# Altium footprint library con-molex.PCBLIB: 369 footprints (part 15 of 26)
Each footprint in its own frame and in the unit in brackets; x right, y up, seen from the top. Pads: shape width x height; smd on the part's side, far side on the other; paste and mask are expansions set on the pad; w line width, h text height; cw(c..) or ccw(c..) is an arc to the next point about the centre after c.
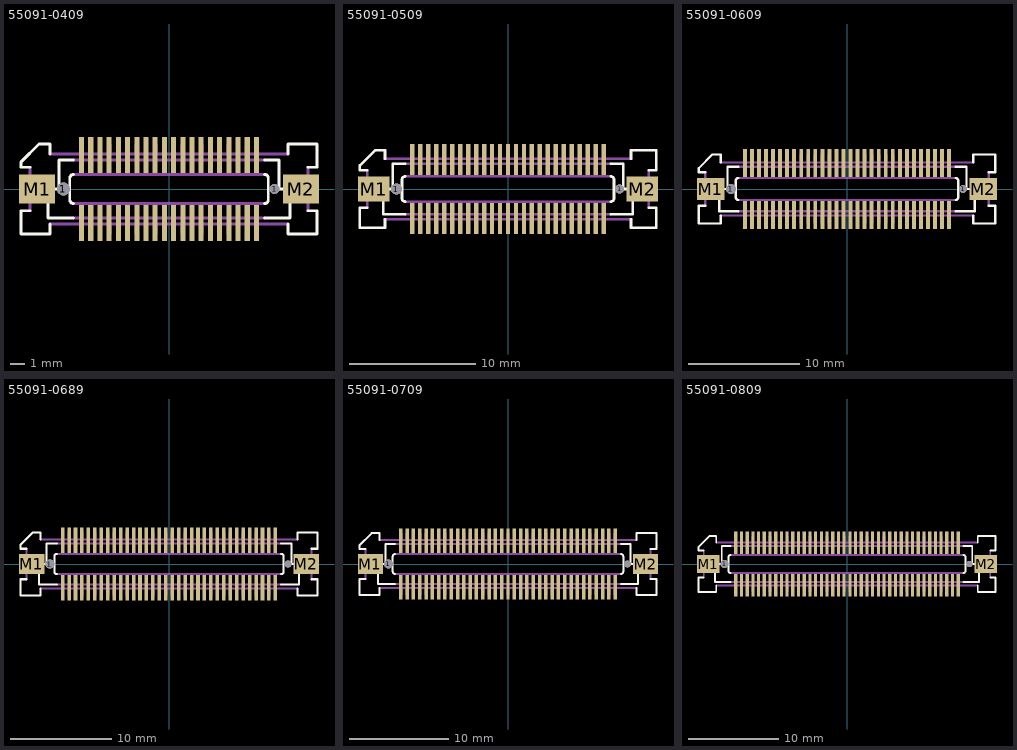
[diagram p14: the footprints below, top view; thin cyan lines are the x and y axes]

## 55091-0409 [mm]
pads (44):
  round 0.9 hole 0.9: 1(-7.285,0)
  rect 0.35x2.5 smd: 1(-6.032,2.35) 2(-6.032,-2.35) 3(-5.397,2.35) 4(-5.397,-2.35) 5(-4.763,2.35) 6(-4.763,-2.35) 7(-4.127,2.35) 8(-4.127,-2.35) 9(-3.492,2.35) 10(-3.492,-2.35) 11(-2.857,2.35) 12(-2.857,-2.35) 13(-2.222,2.35) 14(-2.222,-2.35) 15(-1.587,2.35) 16(-1.587,-2.35) 17(-0.953,2.35) 18(-0.953,-2.35) 19(-0.318,2.35) 20(-0.318,-2.35) 21(0.318,2.35) 22(0.318,-2.35) 23(0.953,2.35) 24(0.953,-2.35) 25(1.587,2.35) 26(1.587,-2.35) 27(2.222,2.35) 28(2.222,-2.35) 29(2.857,2.35) 30(2.857,-2.35) 31(3.492,2.35) 32(3.492,-2.35) 33(4.127,2.35) 34(4.127,-2.35) 35(4.763,2.35) 36(4.763,-2.35) 37(5.397,2.35) 38(5.397,-2.35) 39(6.032,2.35) 40(6.032,-2.35)
  round 0.7 hole 0.7: 1(7.285,0)
  rect 2.5x2 smd: M1(-9.1,0) M2(9.1,0)
Top Overlay:
  lines w0.203: -9.6,-1.5 -10.2,-1.5 -10.2,-3.1 -8.2,-3.1 -8.2,-2.4 ; -9.6,1.5 -10.2,1.5 -10.2,1.875 -8.975,3.1 -8.2,3.1 -8.2,2.4 ; -6.6,-2 -8.35,-2 -8.35,0 -7.6,0 -7.6,2 -6.6,2 ; -6.6,-1 cw(c-6.6,-0.75) -6.85,-0.75 -6.85,0.75 cw(c-6.6,0.75) -6.6,1 ; 6.6,-2 8.35,-2 8.35,0 7.6,0 7.6,2 6.6,2 ; 6.6,-1 ccw(c6.6,-0.75) 6.85,-0.75 6.85,0.75 ccw(c6.6,0.75) 6.6,1 ; 8.2,-2.4 8.2,-3.1 10.2,-3.1 10.2,-1.5 9.6,-1.5 ; 8.2,2.4 8.2,3.1 10.2,3.1 10.2,1.5 9.6,1.5
Top Solder:
  rectangle: -6.232,1.075 -5.833,3.625
  region: -5.833,-1.075 -6.232,-1.075 -6.232,-3.625 -5.833,-3.625
  rectangle: -5.597,1.075 -5.198,3.625
  region: -5.198,-1.075 -5.597,-1.075 -5.597,-3.625 -5.198,-3.625
  rectangle: -4.962,1.075 -4.563,3.625
  region: -4.563,-1.075 -4.962,-1.075 -4.962,-3.625 -4.563,-3.625
  rectangle: -4.327,1.075 -3.928,3.625
  region: -3.928,-1.075 -4.327,-1.075 -4.327,-3.625 -3.928,-3.625
  rectangle: -3.692,1.075 -3.293,3.625
  region: -3.293,-1.075 -3.692,-1.075 -3.692,-3.625 -3.293,-3.625
  rectangle: -3.057,1.075 -2.658,3.625
  region: -2.658,-1.075 -3.057,-1.075 -3.057,-3.625 -2.658,-3.625
  rectangle: -2.422,1.075 -2.023,3.625
  region: -2.023,-1.075 -2.422,-1.075 -2.422,-3.625 -2.023,-3.625
  rectangle: -1.787,1.075 -1.388,3.625
  region: -1.388,-1.075 -1.787,-1.075 -1.787,-3.625 -1.388,-3.625
  rectangle: -1.152,1.075 -0.753,3.625
  region: -0.753,-1.075 -1.152,-1.075 -1.152,-3.625 -0.753,-3.625
  rectangle: -0.517,1.075 -0.118,3.625
  region: -0.118,-1.075 -0.517,-1.075 -0.517,-3.625 -0.118,-3.625
  rectangle: 0.118,1.075 0.517,3.625
  region: 0.517,-1.075 0.118,-1.075 0.118,-3.625 0.517,-3.625
  rectangle: 0.753,1.075 1.152,3.625
  region: 1.152,-1.075 0.753,-1.075 0.753,-3.625 1.152,-3.625
  rectangle: 1.388,1.075 1.787,3.625
  region: 1.787,-1.075 1.388,-1.075 1.388,-3.625 1.787,-3.625
  rectangle: 2.023,1.075 2.422,3.625
  region: 2.422,-1.075 2.023,-1.075 2.023,-3.625 2.422,-3.625
  rectangle: 2.658,1.075 3.057,3.625
  region: 3.057,-1.075 2.658,-1.075 2.658,-3.625 3.057,-3.625
  rectangle: 3.293,1.075 3.692,3.625
  region: 3.692,-1.075 3.293,-1.075 3.293,-3.625 3.692,-3.625
  rectangle: 3.928,1.075 4.327,3.625
  region: 4.327,-1.075 3.928,-1.075 3.928,-3.625 4.327,-3.625
  rectangle: 4.563,1.075 4.962,3.625
  region: 4.962,-1.075 4.563,-1.075 4.563,-3.625 4.962,-3.625
  rectangle: 5.198,1.075 5.597,3.625
  region: 5.597,-1.075 5.198,-1.075 5.198,-3.625 5.597,-3.625
  rectangle: 5.833,1.075 6.232,3.625
  region: 6.232,-1.075 5.833,-1.075 5.833,-3.625 6.232,-3.625
Mechanical 16:
  rectangle: -6.183,-3.1 -5.882,-2.375
  region: -5.882,3.1 -6.183,3.1 -6.183,2.375 -5.882,2.375
  rectangle: -5.548,-3.1 -5.247,-2.375
  region: -5.247,3.1 -5.548,3.1 -5.548,2.375 -5.247,2.375
  rectangle: -4.913,-3.1 -4.612,-2.375
  region: -4.612,3.1 -4.913,3.1 -4.913,2.375 -4.612,2.375
  rectangle: -4.278,-3.1 -3.977,-2.375
  region: -3.977,3.1 -4.278,3.1 -4.278,2.375 -3.977,2.375
  rectangle: -3.643,-3.1 -3.342,-2.375
  region: -3.342,3.1 -3.643,3.1 -3.643,2.375 -3.342,2.375
  rectangle: -3.008,-3.1 -2.707,-2.375
  region: -2.707,3.1 -3.008,3.1 -3.008,2.375 -2.707,2.375
  rectangle: -2.373,-3.1 -2.072,-2.375
  region: -2.072,3.1 -2.373,3.1 -2.373,2.375 -2.072,2.375
  rectangle: -1.738,-3.1 -1.437,-2.375
  region: -1.437,3.1 -1.738,3.1 -1.738,2.375 -1.437,2.375
  rectangle: -1.103,-3.1 -0.802,-2.375
  region: -0.802,3.1 -1.103,3.1 -1.103,2.375 -0.802,2.375
  rectangle: -0.468,-3.1 -0.167,-2.375
  region: -0.167,3.1 -0.468,3.1 -0.468,2.375 -0.167,2.375
  rectangle: 0.167,-3.1 0.468,-2.375
  region: 0.468,3.1 0.167,3.1 0.167,2.375 0.468,2.375
  rectangle: 0.802,-3.1 1.103,-2.375
  region: 1.103,3.1 0.802,3.1 0.802,2.375 1.103,2.375
  rectangle: 1.437,-3.1 1.738,-2.375
  region: 1.738,3.1 1.437,3.1 1.437,2.375 1.738,2.375
  rectangle: 2.072,-3.1 2.373,-2.375
  region: 2.373,3.1 2.072,3.1 2.072,2.375 2.373,2.375
  rectangle: 2.707,-3.1 3.008,-2.375
  region: 3.008,3.1 2.707,3.1 2.707,2.375 3.008,2.375
  rectangle: 3.342,-3.1 3.643,-2.375
  region: 3.643,3.1 3.342,3.1 3.342,2.375 3.643,2.375
  rectangle: 3.977,-3.1 4.278,-2.375
  region: 4.278,3.1 3.977,3.1 3.977,2.375 4.278,2.375
  rectangle: 4.612,-3.1 4.913,-2.375
  region: 4.913,3.1 4.612,3.1 4.612,2.375 4.913,2.375
  rectangle: 5.247,-3.1 5.548,-2.375
  region: 5.548,3.1 5.247,3.1 5.247,2.375 5.548,2.375
  rectangle: 5.882,-3.1 6.183,-2.375
  region: 6.183,3.1 5.882,3.1 5.882,2.375 6.183,2.375
  lines w0.203: -9.6,-1.5 -9.6,1.5 ; -8.2,-2.4 8.2,-2.4 ; -8.2,2.4 8.2,2.4 ; -6.6,-2 6.6,-2 ; -6.6,-1 6.6,-1 ; -6.6,1 6.6,1 ; -6.6,2 6.6,2 ; 9.6,-1.5 9.6,1.5

## 55091-0509 [mm]
pads (54):
  round 0.9 hole 0.9: 1(-8.875,0)
  rect 0.35x2.5 smd: 1(-7.62,2.35) 2(-7.62,-2.35) 3(-6.985,2.35) 4(-6.985,-2.35) 5(-6.35,2.35) 6(-6.35,-2.35) 7(-5.715,2.35) 8(-5.715,-2.35) 9(-5.08,2.35) 10(-5.08,-2.35) 11(-4.445,2.35) 12(-4.445,-2.35) 13(-3.81,2.35) 14(-3.81,-2.35) 15(-3.175,2.35) 16(-3.175,-2.35) 17(-2.54,2.35) 18(-2.54,-2.35) 19(-1.905,2.35) 20(-1.905,-2.35) 21(-1.27,2.35) 22(-1.27,-2.35) 23(-0.635,2.35) 24(-0.635,-2.35) 25(0,2.35) 26(0,-2.35) 27(0.635,2.35) 28(0.635,-2.35) 29(1.27,2.35) 30(1.27,-2.35) 31(1.905,2.35) 32(1.905,-2.35) 33(2.54,2.35) 34(2.54,-2.35) 35(3.175,2.35) 36(3.175,-2.35) 37(3.81,2.35) 38(3.81,-2.35) 39(4.445,2.35) 40(4.445,-2.35) 41(5.08,2.35) 42(5.08,-2.35) 43(5.715,2.35) 44(5.715,-2.35) 45(6.35,2.35) 46(6.35,-2.35) 47(6.985,2.35) 48(6.985,-2.35) 49(7.62,2.35) 50(7.62,-2.35)
  round 0.7 hole 0.7: 1(8.875,0)
  rect 2.5x2 smd: M1(-10.688,0) M2(10.688,0)
Top Overlay:
  lines w0.203: -11.187,-1.5 -11.787,-1.5 -11.787,-3.1 -9.787,-3.1 -9.787,-2.4 ; -11.187,1.5 -11.787,1.5 -11.787,1.875 -10.563,3.1 -9.787,3.1 -9.787,2.4 ; -8.187,-2 -9.937,-2 -9.937,0 -9.187,0 -9.187,2 -8.187,2 ; -8.187,-1 cw(c-8.188,-0.75) -8.438,-0.75 -8.438,0.75 cw(c-8.188,0.75) -8.187,1 ; 8.187,-2 9.937,-2 9.937,0 9.187,0 9.187,2 8.187,2 ; 8.187,-1 ccw(c8.188,-0.75) 8.438,-0.75 8.438,0.75 ccw(c8.188,0.75) 8.187,1 ; 9.787,-2.4 9.787,-3.1 11.787,-3.1 11.787,-1.5 11.187,-1.5 ; 9.787,2.4 9.787,3.1 11.787,3.1 11.787,1.5 11.187,1.5
Top Solder:
  rectangle: -7.82,1.075 -7.42,3.625
  region: -7.42,-1.075 -7.82,-1.075 -7.82,-3.625 -7.42,-3.625
  rectangle: -7.185,1.075 -6.785,3.625
  region: -6.785,-1.075 -7.185,-1.075 -7.185,-3.625 -6.785,-3.625
  rectangle: -6.55,1.075 -6.15,3.625
  region: -6.15,-1.075 -6.55,-1.075 -6.55,-3.625 -6.15,-3.625
  rectangle: -5.915,1.075 -5.515,3.625
  region: -5.515,-1.075 -5.915,-1.075 -5.915,-3.625 -5.515,-3.625
  rectangle: -5.28,1.075 -4.88,3.625
  region: -4.88,-1.075 -5.28,-1.075 -5.28,-3.625 -4.88,-3.625
  rectangle: -4.645,1.075 -4.245,3.625
  region: -4.245,-1.075 -4.645,-1.075 -4.645,-3.625 -4.245,-3.625
  rectangle: -4.01,1.075 -3.61,3.625
  region: -3.61,-1.075 -4.01,-1.075 -4.01,-3.625 -3.61,-3.625
  rectangle: -3.375,1.075 -2.975,3.625
  region: -2.975,-1.075 -3.375,-1.075 -3.375,-3.625 -2.975,-3.625
  rectangle: -2.74,1.075 -2.34,3.625
  region: -2.34,-1.075 -2.74,-1.075 -2.74,-3.625 -2.34,-3.625
  rectangle: -2.105,1.075 -1.705,3.625
  region: -1.705,-1.075 -2.105,-1.075 -2.105,-3.625 -1.705,-3.625
  rectangle: -1.47,1.075 -1.07,3.625
  region: -1.07,-1.075 -1.47,-1.075 -1.47,-3.625 -1.07,-3.625
  rectangle: -0.835,1.075 -0.435,3.625
  region: -0.435,-1.075 -0.835,-1.075 -0.835,-3.625 -0.435,-3.625
  rectangle: -0.2,1.075 0.2,3.625
  region: 0.2,-1.075 -0.2,-1.075 -0.2,-3.625 0.2,-3.625
  rectangle: 0.435,1.075 0.835,3.625
  region: 0.835,-1.075 0.435,-1.075 0.435,-3.625 0.835,-3.625
  rectangle: 1.07,1.075 1.47,3.625
  region: 1.47,-1.075 1.07,-1.075 1.07,-3.625 1.47,-3.625
  rectangle: 1.705,1.075 2.105,3.625
  region: 2.105,-1.075 1.705,-1.075 1.705,-3.625 2.105,-3.625
  rectangle: 2.34,1.075 2.74,3.625
  region: 2.74,-1.075 2.34,-1.075 2.34,-3.625 2.74,-3.625
  rectangle: 2.975,1.075 3.375,3.625
  region: 3.375,-1.075 2.975,-1.075 2.975,-3.625 3.375,-3.625
  rectangle: 3.61,1.075 4.01,3.625
  region: 4.01,-1.075 3.61,-1.075 3.61,-3.625 4.01,-3.625
  rectangle: 4.245,1.075 4.645,3.625
  region: 4.645,-1.075 4.245,-1.075 4.245,-3.625 4.645,-3.625
  rectangle: 4.88,1.075 5.28,3.625
  region: 5.28,-1.075 4.88,-1.075 4.88,-3.625 5.28,-3.625
  rectangle: 5.515,1.075 5.915,3.625
  region: 5.915,-1.075 5.515,-1.075 5.515,-3.625 5.915,-3.625
  rectangle: 6.15,1.075 6.55,3.625
  region: 6.55,-1.075 6.15,-1.075 6.15,-3.625 6.55,-3.625
  rectangle: 6.785,1.075 7.185,3.625
  region: 7.185,-1.075 6.785,-1.075 6.785,-3.625 7.185,-3.625
  rectangle: 7.42,1.075 7.82,3.625
  region: 7.82,-1.075 7.42,-1.075 7.42,-3.625 7.82,-3.625
Mechanical 16:
  rectangle: -7.77,-3.1 -7.47,-2.375
  region: -7.47,3.1 -7.77,3.1 -7.77,2.375 -7.47,2.375
  rectangle: -7.135,-3.1 -6.835,-2.375
  region: -6.835,3.1 -7.135,3.1 -7.135,2.375 -6.835,2.375
  rectangle: -6.5,-3.1 -6.2,-2.375
  region: -6.2,3.1 -6.5,3.1 -6.5,2.375 -6.2,2.375
  rectangle: -5.865,-3.1 -5.565,-2.375
  region: -5.565,3.1 -5.865,3.1 -5.865,2.375 -5.565,2.375
  rectangle: -5.23,-3.1 -4.93,-2.375
  region: -4.93,3.1 -5.23,3.1 -5.23,2.375 -4.93,2.375
  rectangle: -4.595,-3.1 -4.295,-2.375
  region: -4.295,3.1 -4.595,3.1 -4.595,2.375 -4.295,2.375
  rectangle: -3.96,-3.1 -3.66,-2.375
  region: -3.66,3.1 -3.96,3.1 -3.96,2.375 -3.66,2.375
  rectangle: -3.325,-3.1 -3.025,-2.375
  region: -3.025,3.1 -3.325,3.1 -3.325,2.375 -3.025,2.375
  rectangle: -2.69,-3.1 -2.39,-2.375
  region: -2.39,3.1 -2.69,3.1 -2.69,2.375 -2.39,2.375
  rectangle: -2.055,-3.1 -1.755,-2.375
  region: -1.755,3.1 -2.055,3.1 -2.055,2.375 -1.755,2.375
  rectangle: -1.42,-3.1 -1.12,-2.375
  region: -1.12,3.1 -1.42,3.1 -1.42,2.375 -1.12,2.375
  rectangle: -0.785,-3.1 -0.485,-2.375
  region: -0.485,3.1 -0.785,3.1 -0.785,2.375 -0.485,2.375
  rectangle: -0.15,-3.1 0.15,-2.375
  region: 0.15,3.1 -0.15,3.1 -0.15,2.375 0.15,2.375
  rectangle: 0.485,-3.1 0.785,-2.375
  region: 0.785,3.1 0.485,3.1 0.485,2.375 0.785,2.375
  rectangle: 1.12,-3.1 1.42,-2.375
  region: 1.42,3.1 1.12,3.1 1.12,2.375 1.42,2.375
  rectangle: 1.755,-3.1 2.055,-2.375
  region: 2.055,3.1 1.755,3.1 1.755,2.375 2.055,2.375
  rectangle: 2.39,-3.1 2.69,-2.375
  region: 2.69,3.1 2.39,3.1 2.39,2.375 2.69,2.375
  rectangle: 3.025,-3.1 3.325,-2.375
  region: 3.325,3.1 3.025,3.1 3.025,2.375 3.325,2.375
  rectangle: 3.66,-3.1 3.96,-2.375
  region: 3.96,3.1 3.66,3.1 3.66,2.375 3.96,2.375
  rectangle: 4.295,-3.1 4.595,-2.375
  region: 4.595,3.1 4.295,3.1 4.295,2.375 4.595,2.375
  rectangle: 4.93,-3.1 5.23,-2.375
  region: 5.23,3.1 4.93,3.1 4.93,2.375 5.23,2.375
  rectangle: 5.565,-3.1 5.865,-2.375
  region: 5.865,3.1 5.565,3.1 5.565,2.375 5.865,2.375
  rectangle: 6.2,-3.1 6.5,-2.375
  region: 6.5,3.1 6.2,3.1 6.2,2.375 6.5,2.375
  rectangle: 6.835,-3.1 7.135,-2.375
  region: 7.135,3.1 6.835,3.1 6.835,2.375 7.135,2.375
  rectangle: 7.47,-3.1 7.77,-2.375
  region: 7.77,3.1 7.47,3.1 7.47,2.375 7.77,2.375
  lines w0.203: -11.187,-1.5 -11.187,1.5 ; -9.787,-2.4 9.787,-2.4 ; -9.787,2.4 9.787,2.4 ; -8.187,-2 8.187,-2 ; -8.187,-1 8.187,-1 ; -8.187,1 8.187,1 ; -8.187,2 8.187,2 ; 11.187,-1.5 11.187,1.5

## 55091-0609 [mm]
pads (64):
  round 0.9 hole 0.9: 1(-10.46,0)
  rect 0.35x2.5 smd: 1(-9.207,2.35) 2(-9.207,-2.35) 3(-8.572,2.35) 4(-8.572,-2.35) 5(-7.938,2.35) 6(-7.938,-2.35) 7(-7.302,2.35) 8(-7.302,-2.35) 9(-6.667,2.35) 10(-6.667,-2.35) 11(-6.032,2.35) 12(-6.032,-2.35) 13(-5.397,2.35) 14(-5.397,-2.35) 15(-4.763,2.35) 16(-4.763,-2.35) 17(-4.127,2.35) 18(-4.127,-2.35) 19(-3.492,2.35) 20(-3.492,-2.35) 21(-2.857,2.35) 22(-2.857,-2.35) 23(-2.222,2.35) 24(-2.222,-2.35) 25(-1.587,2.35) 26(-1.587,-2.35) 27(-0.953,2.35) 28(-0.953,-2.35) 29(-0.318,2.35) 30(-0.318,-2.35) 31(0.318,2.35) 32(0.318,-2.35) 33(0.953,2.35) 34(0.953,-2.35) 35(1.587,2.35) 36(1.587,-2.35) 37(2.222,2.35) 38(2.222,-2.35) 39(2.857,2.35) 40(2.857,-2.35) 41(3.492,2.35) 42(3.492,-2.35) 43(4.127,2.35) 44(4.127,-2.35) 45(4.763,2.35) 46(4.763,-2.35) 47(5.397,2.35) 48(5.397,-2.35) 49(6.032,2.35) 50(6.032,-2.35) 51(6.667,2.35) 52(6.667,-2.35) 53(7.302,2.35) 54(7.302,-2.35) 55(7.938,2.35) 56(7.938,-2.35) 57(8.572,2.35) 58(8.572,-2.35) 59(9.207,2.35) 60(9.207,-2.35)
  round 0.7 hole 0.7: 1(10.46,0)
  rect 2.5x2 smd: M1(-12.275,0) M2(12.275,0)
Top Overlay:
  lines w0.203: -12.775,-1.5 -13.375,-1.5 -13.375,-3.1 -11.375,-3.1 -11.375,-2.4 ; -12.775,1.5 -13.375,1.5 -13.375,1.875 -12.15,3.1 -11.375,3.1 -11.375,2.4 ; -9.775,-2 -11.525,-2 -11.525,0 -10.775,0 -10.775,2 -9.775,2 ; -9.775,-1 cw(c-9.775,-0.75) -10.025,-0.75 -10.025,0.75 cw(c-9.775,0.75) -9.775,1 ; 9.775,-2 11.525,-2 11.525,0 10.775,0 10.775,2 9.775,2 ; 9.775,-1 ccw(c9.775,-0.75) 10.025,-0.75 10.025,0.75 ccw(c9.775,0.75) 9.775,1 ; 11.375,-2.4 11.375,-3.1 13.375,-3.1 13.375,-1.5 12.775,-1.5 ; 11.375,2.4 11.375,3.1 13.375,3.1 13.375,1.5 12.775,1.5
Top Solder:
  rectangle: -9.407,1.075 -9.008,3.625
  region: -9.008,-1.075 -9.407,-1.075 -9.407,-3.625 -9.008,-3.625
  rectangle: -8.772,1.075 -8.373,3.625
  region: -8.373,-1.075 -8.772,-1.075 -8.772,-3.625 -8.373,-3.625
  rectangle: -8.137,1.075 -7.738,3.625
  region: -7.738,-1.075 -8.137,-1.075 -8.137,-3.625 -7.738,-3.625
  rectangle: -7.502,1.075 -7.103,3.625
  region: -7.103,-1.075 -7.502,-1.075 -7.502,-3.625 -7.103,-3.625
  rectangle: -6.867,1.075 -6.468,3.625
  region: -6.468,-1.075 -6.867,-1.075 -6.867,-3.625 -6.468,-3.625
  rectangle: -6.232,1.075 -5.833,3.625
  region: -5.833,-1.075 -6.232,-1.075 -6.232,-3.625 -5.833,-3.625
  rectangle: -5.597,1.075 -5.198,3.625
  region: -5.198,-1.075 -5.597,-1.075 -5.597,-3.625 -5.198,-3.625
  rectangle: -4.962,1.075 -4.563,3.625
  region: -4.563,-1.075 -4.962,-1.075 -4.962,-3.625 -4.563,-3.625
  rectangle: -4.327,1.075 -3.928,3.625
  region: -3.928,-1.075 -4.327,-1.075 -4.327,-3.625 -3.928,-3.625
  rectangle: -3.692,1.075 -3.293,3.625
  region: -3.293,-1.075 -3.692,-1.075 -3.692,-3.625 -3.293,-3.625
  rectangle: -3.057,1.075 -2.658,3.625
  region: -2.658,-1.075 -3.057,-1.075 -3.057,-3.625 -2.658,-3.625
  rectangle: -2.422,1.075 -2.023,3.625
  region: -2.023,-1.075 -2.422,-1.075 -2.422,-3.625 -2.023,-3.625
  rectangle: -1.787,1.075 -1.388,3.625
  region: -1.388,-1.075 -1.787,-1.075 -1.787,-3.625 -1.388,-3.625
  rectangle: -1.152,1.075 -0.753,3.625
  region: -0.753,-1.075 -1.152,-1.075 -1.152,-3.625 -0.753,-3.625
  rectangle: -0.517,1.075 -0.118,3.625
  region: -0.118,-1.075 -0.517,-1.075 -0.517,-3.625 -0.118,-3.625
  rectangle: 0.118,1.075 0.517,3.625
  region: 0.517,-1.075 0.118,-1.075 0.118,-3.625 0.517,-3.625
  rectangle: 0.753,1.075 1.152,3.625
  region: 1.152,-1.075 0.753,-1.075 0.753,-3.625 1.152,-3.625
  rectangle: 1.388,1.075 1.787,3.625
  region: 1.787,-1.075 1.388,-1.075 1.388,-3.625 1.787,-3.625
  rectangle: 2.023,1.075 2.422,3.625
  region: 2.422,-1.075 2.023,-1.075 2.023,-3.625 2.422,-3.625
  rectangle: 2.658,1.075 3.057,3.625
  region: 3.057,-1.075 2.658,-1.075 2.658,-3.625 3.057,-3.625
  rectangle: 3.293,1.075 3.692,3.625
  region: 3.692,-1.075 3.293,-1.075 3.293,-3.625 3.692,-3.625
  rectangle: 3.928,1.075 4.327,3.625
  region: 4.327,-1.075 3.928,-1.075 3.928,-3.625 4.327,-3.625
  rectangle: 4.563,1.075 4.962,3.625
  region: 4.962,-1.075 4.563,-1.075 4.563,-3.625 4.962,-3.625
  rectangle: 5.198,1.075 5.597,3.625
  region: 5.597,-1.075 5.198,-1.075 5.198,-3.625 5.597,-3.625
  rectangle: 5.833,1.075 6.232,3.625
  region: 6.232,-1.075 5.833,-1.075 5.833,-3.625 6.232,-3.625
  rectangle: 6.468,1.075 6.867,3.625
  region: 6.867,-1.075 6.468,-1.075 6.468,-3.625 6.867,-3.625
  rectangle: 7.103,1.075 7.502,3.625
  region: 7.502,-1.075 7.103,-1.075 7.103,-3.625 7.502,-3.625
  rectangle: 7.738,1.075 8.137,3.625
  region: 8.137,-1.075 7.738,-1.075 7.738,-3.625 8.137,-3.625
  rectangle: 8.373,1.075 8.772,3.625
  region: 8.772,-1.075 8.373,-1.075 8.373,-3.625 8.772,-3.625
  rectangle: 9.008,1.075 9.407,3.625
  region: 9.407,-1.075 9.008,-1.075 9.008,-3.625 9.407,-3.625
Mechanical 16:
  rectangle: -9.358,-3.1 -9.057,-2.375
  region: -9.057,3.1 -9.358,3.1 -9.358,2.375 -9.057,2.375
  rectangle: -8.723,-3.1 -8.422,-2.375
  region: -8.422,3.1 -8.723,3.1 -8.723,2.375 -8.422,2.375
  rectangle: -8.088,-3.1 -7.787,-2.375
  region: -7.787,3.1 -8.088,3.1 -8.088,2.375 -7.787,2.375
  rectangle: -7.453,-3.1 -7.152,-2.375
  region: -7.152,3.1 -7.453,3.1 -7.453,2.375 -7.152,2.375
  rectangle: -6.818,-3.1 -6.517,-2.375
  region: -6.517,3.1 -6.818,3.1 -6.818,2.375 -6.517,2.375
  rectangle: -6.183,-3.1 -5.882,-2.375
  region: -5.882,3.1 -6.183,3.1 -6.183,2.375 -5.882,2.375
  rectangle: -5.548,-3.1 -5.247,-2.375
  region: -5.247,3.1 -5.548,3.1 -5.548,2.375 -5.247,2.375
  rectangle: -4.913,-3.1 -4.612,-2.375
  region: -4.612,3.1 -4.913,3.1 -4.913,2.375 -4.612,2.375
  rectangle: -4.278,-3.1 -3.977,-2.375
  region: -3.977,3.1 -4.278,3.1 -4.278,2.375 -3.977,2.375
  rectangle: -3.643,-3.1 -3.342,-2.375
  region: -3.342,3.1 -3.643,3.1 -3.643,2.375 -3.342,2.375
  rectangle: -3.008,-3.1 -2.707,-2.375
  region: -2.707,3.1 -3.008,3.1 -3.008,2.375 -2.707,2.375
  rectangle: -2.373,-3.1 -2.072,-2.375
  region: -2.072,3.1 -2.373,3.1 -2.373,2.375 -2.072,2.375
  rectangle: -1.738,-3.1 -1.437,-2.375
  region: -1.437,3.1 -1.738,3.1 -1.738,2.375 -1.437,2.375
  rectangle: -1.103,-3.1 -0.802,-2.375
  region: -0.802,3.1 -1.103,3.1 -1.103,2.375 -0.802,2.375
  rectangle: -0.468,-3.1 -0.167,-2.375
  region: -0.167,3.1 -0.468,3.1 -0.468,2.375 -0.167,2.375
  rectangle: 0.167,-3.1 0.468,-2.375
  region: 0.468,3.1 0.167,3.1 0.167,2.375 0.468,2.375
  rectangle: 0.802,-3.1 1.103,-2.375
  region: 1.103,3.1 0.802,3.1 0.802,2.375 1.103,2.375
  rectangle: 1.437,-3.1 1.738,-2.375
  region: 1.738,3.1 1.437,3.1 1.437,2.375 1.738,2.375
  rectangle: 2.072,-3.1 2.373,-2.375
  region: 2.373,3.1 2.072,3.1 2.072,2.375 2.373,2.375
  rectangle: 2.707,-3.1 3.008,-2.375
  region: 3.008,3.1 2.707,3.1 2.707,2.375 3.008,2.375
  rectangle: 3.342,-3.1 3.643,-2.375
  region: 3.643,3.1 3.342,3.1 3.342,2.375 3.643,2.375
  rectangle: 3.977,-3.1 4.278,-2.375
  region: 4.278,3.1 3.977,3.1 3.977,2.375 4.278,2.375
  rectangle: 4.612,-3.1 4.913,-2.375
  region: 4.913,3.1 4.612,3.1 4.612,2.375 4.913,2.375
  rectangle: 5.247,-3.1 5.548,-2.375
  region: 5.548,3.1 5.247,3.1 5.247,2.375 5.548,2.375
  rectangle: 5.882,-3.1 6.183,-2.375
  region: 6.183,3.1 5.882,3.1 5.882,2.375 6.183,2.375
  rectangle: 6.517,-3.1 6.818,-2.375
  region: 6.818,3.1 6.517,3.1 6.517,2.375 6.818,2.375
  rectangle: 7.152,-3.1 7.453,-2.375
  region: 7.453,3.1 7.152,3.1 7.152,2.375 7.453,2.375
  rectangle: 7.787,-3.1 8.088,-2.375
  region: 8.088,3.1 7.787,3.1 7.787,2.375 8.088,2.375
  rectangle: 8.422,-3.1 8.723,-2.375
  region: 8.723,3.1 8.422,3.1 8.422,2.375 8.723,2.375
  rectangle: 9.057,-3.1 9.358,-2.375
  region: 9.358,3.1 9.057,3.1 9.057,2.375 9.358,2.375
  lines w0.203: -12.775,-1.5 -12.775,1.5 ; -11.375,-2.4 11.375,-2.4 ; -11.375,2.4 11.375,2.4 ; -9.775,-2 9.775,-2 ; -9.775,-1 9.775,-1 ; -9.775,1 9.775,1 ; -9.775,2 9.775,2 ; 12.775,-1.5 12.775,1.5

## 55091-0689 [mm]
pads (72):
  round 0.9 hole 0.9: 1(-11.73,0)
  rect 0.35x2.5 smd: 1(-10.477,2.35) 2(-10.477,-2.35) 3(-9.842,2.35) 4(-9.842,-2.35) 5(-9.207,2.35) 6(-9.207,-2.35) 7(-8.572,2.35) 8(-8.572,-2.35) 9(-7.938,2.35) 10(-7.938,-2.35) 11(-7.302,2.35) 12(-7.302,-2.35) 13(-6.667,2.35) 14(-6.667,-2.35) 15(-6.032,2.35) 16(-6.032,-2.35) 17(-5.397,2.35) 18(-5.397,-2.35) 19(-4.763,2.35) 20(-4.763,-2.35) 21(-4.127,2.35) 22(-4.127,-2.35) 23(-3.492,2.35) 24(-3.492,-2.35) 25(-2.857,2.35) 26(-2.857,-2.35) 27(-2.222,2.35) 28(-2.222,-2.35) 29(-1.587,2.35) 30(-1.587,-2.35) 31(-0.953,2.35) 32(-0.953,-2.35) 33(-0.318,2.35) 34(-0.318,-2.35) 35(0.318,2.35) 36(0.318,-2.35) 37(0.953,2.35) 38(0.953,-2.35) 39(1.587,2.35) 40(1.587,-2.35) 41(2.222,2.35) 42(2.222,-2.35) 43(2.857,2.35) 44(2.857,-2.35) 45(3.492,2.35) 46(3.492,-2.35) 47(4.127,2.35) 48(4.127,-2.35) 49(4.763,2.35) 50(4.763,-2.35) 51(5.397,2.35) 52(5.397,-2.35) 53(6.032,2.35) 54(6.032,-2.35) 55(6.667,2.35) 56(6.667,-2.35) 57(7.302,2.35) 58(7.302,-2.35) 59(7.938,2.35) 60(7.938,-2.35) 61(8.572,2.35) 62(8.572,-2.35) 63(9.207,2.35) 64(9.207,-2.35) 65(9.842,2.35) 66(9.842,-2.35) 67(10.477,2.35) 68(10.477,-2.35)
  round 0.7 hole 0.7: 1(11.73,0)
  rect 2.5x2 smd: M1(-13.525,0) M2(13.525,0)
Top Overlay:
  lines w0.203: -14.045,-1.5 -14.645,-1.5 -14.645,-3.1 -12.645,-3.1 -12.645,-2.4 ; -14.045,1.5 -14.645,1.5 -14.645,1.875 -13.42,3.1 -12.645,3.1 -12.645,2.4 ; -11.045,-2 -12.795,-2 -12.795,0 -12.045,0 -12.045,2 -11.045,2 ; -11.045,-1 cw(c-11.045,-0.75) -11.295,-0.75 -11.295,0.75 cw(c-11.045,0.75) -11.045,1 ; 11.045,-2 12.795,-2 12.795,0 12.045,0 12.045,2 11.045,2 ; 11.045,-1 ccw(c11.045,-0.75) 11.295,-0.75 11.295,0.75 ccw(c11.045,0.75) 11.045,1 ; 12.645,-2.4 12.645,-3.1 14.645,-3.1 14.645,-1.5 14.045,-1.5 ; 12.645,2.4 12.645,3.1 14.645,3.1 14.645,1.5 14.045,1.5
Top Solder:
  rectangle: -10.677,1.075 -10.278,3.625
  region: -10.278,-1.075 -10.677,-1.075 -10.677,-3.625 -10.278,-3.625
  rectangle: -10.042,1.075 -9.643,3.625
  region: -9.643,-1.075 -10.042,-1.075 -10.042,-3.625 -9.643,-3.625
  rectangle: -9.407,1.075 -9.008,3.625
  region: -9.008,-1.075 -9.407,-1.075 -9.407,-3.625 -9.008,-3.625
  rectangle: -8.772,1.075 -8.373,3.625
  region: -8.373,-1.075 -8.772,-1.075 -8.772,-3.625 -8.373,-3.625
  rectangle: -8.137,1.075 -7.738,3.625
  region: -7.738,-1.075 -8.137,-1.075 -8.137,-3.625 -7.738,-3.625
  rectangle: -7.502,1.075 -7.103,3.625
  region: -7.103,-1.075 -7.502,-1.075 -7.502,-3.625 -7.103,-3.625
  rectangle: -6.867,1.075 -6.468,3.625
  region: -6.468,-1.075 -6.867,-1.075 -6.867,-3.625 -6.468,-3.625
  rectangle: -6.232,1.075 -5.833,3.625
  region: -5.833,-1.075 -6.232,-1.075 -6.232,-3.625 -5.833,-3.625
  rectangle: -5.597,1.075 -5.198,3.625
  region: -5.198,-1.075 -5.597,-1.075 -5.597,-3.625 -5.198,-3.625
  rectangle: -4.962,1.075 -4.563,3.625
  region: -4.563,-1.075 -4.962,-1.075 -4.962,-3.625 -4.563,-3.625
  rectangle: -4.327,1.075 -3.928,3.625
  region: -3.928,-1.075 -4.327,-1.075 -4.327,-3.625 -3.928,-3.625
  rectangle: -3.692,1.075 -3.293,3.625
  region: -3.293,-1.075 -3.692,-1.075 -3.692,-3.625 -3.293,-3.625
  rectangle: -3.057,1.075 -2.658,3.625
  region: -2.658,-1.075 -3.057,-1.075 -3.057,-3.625 -2.658,-3.625
  rectangle: -2.422,1.075 -2.023,3.625
  region: -2.023,-1.075 -2.422,-1.075 -2.422,-3.625 -2.023,-3.625
  rectangle: -1.787,1.075 -1.388,3.625
  region: -1.388,-1.075 -1.787,-1.075 -1.787,-3.625 -1.388,-3.625
  rectangle: -1.152,1.075 -0.753,3.625
  region: -0.753,-1.075 -1.152,-1.075 -1.152,-3.625 -0.753,-3.625
  rectangle: -0.517,1.075 -0.118,3.625
  region: -0.118,-1.075 -0.517,-1.075 -0.517,-3.625 -0.118,-3.625
  rectangle: 0.118,1.075 0.517,3.625
  region: 0.517,-1.075 0.118,-1.075 0.118,-3.625 0.517,-3.625
  rectangle: 0.753,1.075 1.152,3.625
  region: 1.152,-1.075 0.753,-1.075 0.753,-3.625 1.152,-3.625
  rectangle: 1.388,1.075 1.787,3.625
  region: 1.787,-1.075 1.388,-1.075 1.388,-3.625 1.787,-3.625
  rectangle: 2.023,1.075 2.422,3.625
  region: 2.422,-1.075 2.023,-1.075 2.023,-3.625 2.422,-3.625
  rectangle: 2.658,1.075 3.057,3.625
  region: 3.057,-1.075 2.658,-1.075 2.658,-3.625 3.057,-3.625
  rectangle: 3.293,1.075 3.692,3.625
  region: 3.692,-1.075 3.293,-1.075 3.293,-3.625 3.692,-3.625
  rectangle: 3.928,1.075 4.327,3.625
  region: 4.327,-1.075 3.928,-1.075 3.928,-3.625 4.327,-3.625
  rectangle: 4.563,1.075 4.962,3.625
  region: 4.962,-1.075 4.563,-1.075 4.563,-3.625 4.962,-3.625
  rectangle: 5.198,1.075 5.597,3.625
  region: 5.597,-1.075 5.198,-1.075 5.198,-3.625 5.597,-3.625
  rectangle: 5.833,1.075 6.232,3.625
  region: 6.232,-1.075 5.833,-1.075 5.833,-3.625 6.232,-3.625
  rectangle: 6.468,1.075 6.867,3.625
  region: 6.867,-1.075 6.468,-1.075 6.468,-3.625 6.867,-3.625
  rectangle: 7.103,1.075 7.502,3.625
  region: 7.502,-1.075 7.103,-1.075 7.103,-3.625 7.502,-3.625
  rectangle: 7.738,1.075 8.137,3.625
  region: 8.137,-1.075 7.738,-1.075 7.738,-3.625 8.137,-3.625
  rectangle: 8.373,1.075 8.772,3.625
  region: 8.772,-1.075 8.373,-1.075 8.373,-3.625 8.772,-3.625
  rectangle: 9.008,1.075 9.407,3.625
  region: 9.407,-1.075 9.008,-1.075 9.008,-3.625 9.407,-3.625
  rectangle: 9.643,1.075 10.042,3.625
  region: 10.042,-1.075 9.643,-1.075 9.643,-3.625 10.042,-3.625
  rectangle: 10.278,1.075 10.677,3.625
  region: 10.677,-1.075 10.278,-1.075 10.278,-3.625 10.677,-3.625
Mechanical 16:
  rectangle: -10.628,-3.1 -10.327,-2.375
  region: -10.327,3.1 -10.628,3.1 -10.628,2.375 -10.327,2.375
  rectangle: -9.993,-3.1 -9.692,-2.375
  region: -9.692,3.1 -9.993,3.1 -9.993,2.375 -9.692,2.375
  rectangle: -9.358,-3.1 -9.057,-2.375
  region: -9.057,3.1 -9.358,3.1 -9.358,2.375 -9.057,2.375
  rectangle: -8.723,-3.1 -8.422,-2.375
  region: -8.422,3.1 -8.723,3.1 -8.723,2.375 -8.422,2.375
  rectangle: -8.088,-3.1 -7.787,-2.375
  region: -7.787,3.1 -8.088,3.1 -8.088,2.375 -7.787,2.375
  rectangle: -7.453,-3.1 -7.152,-2.375
  region: -7.152,3.1 -7.453,3.1 -7.453,2.375 -7.152,2.375
  rectangle: -6.818,-3.1 -6.517,-2.375
  region: -6.517,3.1 -6.818,3.1 -6.818,2.375 -6.517,2.375
  rectangle: -6.183,-3.1 -5.882,-2.375
  region: -5.882,3.1 -6.183,3.1 -6.183,2.375 -5.882,2.375
  rectangle: -5.548,-3.1 -5.247,-2.375
  region: -5.247,3.1 -5.548,3.1 -5.548,2.375 -5.247,2.375
  rectangle: -4.913,-3.1 -4.612,-2.375
  region: -4.612,3.1 -4.913,3.1 -4.913,2.375 -4.612,2.375
  rectangle: -4.278,-3.1 -3.977,-2.375
  region: -3.977,3.1 -4.278,3.1 -4.278,2.375 -3.977,2.375
  rectangle: -3.643,-3.1 -3.342,-2.375
  region: -3.342,3.1 -3.643,3.1 -3.643,2.375 -3.342,2.375
  rectangle: -3.008,-3.1 -2.707,-2.375
  region: -2.707,3.1 -3.008,3.1 -3.008,2.375 -2.707,2.375
  rectangle: -2.373,-3.1 -2.072,-2.375
  region: -2.072,3.1 -2.373,3.1 -2.373,2.375 -2.072,2.375
  rectangle: -1.738,-3.1 -1.437,-2.375
  region: -1.437,3.1 -1.738,3.1 -1.738,2.375 -1.437,2.375
  rectangle: -1.103,-3.1 -0.802,-2.375
  region: -0.802,3.1 -1.103,3.1 -1.103,2.375 -0.802,2.375
  rectangle: -0.468,-3.1 -0.167,-2.375
  region: -0.167,3.1 -0.468,3.1 -0.468,2.375 -0.167,2.375
  rectangle: 0.167,-3.1 0.468,-2.375
  region: 0.468,3.1 0.167,3.1 0.167,2.375 0.468,2.375
  rectangle: 0.802,-3.1 1.103,-2.375
  region: 1.103,3.1 0.802,3.1 0.802,2.375 1.103,2.375
  rectangle: 1.437,-3.1 1.738,-2.375
  region: 1.738,3.1 1.437,3.1 1.437,2.375 1.738,2.375
  rectangle: 2.072,-3.1 2.373,-2.375
  region: 2.373,3.1 2.072,3.1 2.072,2.375 2.373,2.375
  rectangle: 2.707,-3.1 3.008,-2.375
  region: 3.008,3.1 2.707,3.1 2.707,2.375 3.008,2.375
  rectangle: 3.342,-3.1 3.643,-2.375
  region: 3.643,3.1 3.342,3.1 3.342,2.375 3.643,2.375
  rectangle: 3.977,-3.1 4.278,-2.375
  region: 4.278,3.1 3.977,3.1 3.977,2.375 4.278,2.375
  rectangle: 4.612,-3.1 4.913,-2.375
  region: 4.913,3.1 4.612,3.1 4.612,2.375 4.913,2.375
  rectangle: 5.247,-3.1 5.548,-2.375
  region: 5.548,3.1 5.247,3.1 5.247,2.375 5.548,2.375
  rectangle: 5.882,-3.1 6.183,-2.375
  region: 6.183,3.1 5.882,3.1 5.882,2.375 6.183,2.375
  rectangle: 6.517,-3.1 6.818,-2.375
  region: 6.818,3.1 6.517,3.1 6.517,2.375 6.818,2.375
  rectangle: 7.152,-3.1 7.453,-2.375
  region: 7.453,3.1 7.152,3.1 7.152,2.375 7.453,2.375
  rectangle: 7.787,-3.1 8.088,-2.375
  region: 8.088,3.1 7.787,3.1 7.787,2.375 8.088,2.375
  rectangle: 8.422,-3.1 8.723,-2.375
  region: 8.723,3.1 8.422,3.1 8.422,2.375 8.723,2.375
  rectangle: 9.057,-3.1 9.358,-2.375
  region: 9.358,3.1 9.057,3.1 9.057,2.375 9.358,2.375
  rectangle: 9.692,-3.1 9.993,-2.375
  region: 9.993,3.1 9.692,3.1 9.692,2.375 9.993,2.375
  rectangle: 10.327,-3.1 10.628,-2.375
  region: 10.628,3.1 10.327,3.1 10.327,2.375 10.628,2.375
  lines w0.203: -14.045,-1.5 -14.045,1.5 ; -12.645,-2.4 12.645,-2.4 ; -12.645,2.4 12.645,2.4 ; -11.045,-2 11.045,-2 ; -11.045,-1 11.045,-1 ; -11.045,1 11.045,1 ; -11.045,2 11.045,2 ; 14.045,-1.5 14.045,1.5

## 55091-0709 [mm]
pads (74):
  round 0.9 hole 0.9: 1(-12.05,0)
  rect 0.35x2.5 smd: 1(-10.795,2.35) 2(-10.795,-2.35) 3(-10.16,2.35) 4(-10.16,-2.35) 5(-9.525,2.35) 6(-9.525,-2.35) 7(-8.89,2.35) 8(-8.89,-2.35) 9(-8.255,2.35) 10(-8.255,-2.35) 11(-7.62,2.35) 12(-7.62,-2.35) 13(-6.985,2.35) 14(-6.985,-2.35) 15(-6.35,2.35) 16(-6.35,-2.35) 17(-5.715,2.35) 18(-5.715,-2.35) 19(-5.08,2.35) 20(-5.08,-2.35) 21(-4.445,2.35) 22(-4.445,-2.35) 23(-3.81,2.35) 24(-3.81,-2.35) 25(-3.175,2.35) 26(-3.175,-2.35) 27(-2.54,2.35) 28(-2.54,-2.35) 29(-1.905,2.35) 30(-1.905,-2.35) 31(-1.27,2.35) 32(-1.27,-2.35) 33(-0.635,2.35) 34(-0.635,-2.35) 35(0,2.35) 36(0,-2.35) 37(0.635,2.35) 38(0.635,-2.35) 39(1.27,2.35) 40(1.27,-2.35) 41(1.905,2.35) 42(1.905,-2.35) 43(2.54,2.35) 44(2.54,-2.35) 45(3.175,2.35) 46(3.175,-2.35) 47(3.81,2.35) 48(3.81,-2.35) 49(4.445,2.35) 50(4.445,-2.35) 51(5.08,2.35) 52(5.08,-2.35) 53(5.715,2.35) 54(5.715,-2.35) 55(6.35,2.35) 56(6.35,-2.35) 57(6.985,2.35) 58(6.985,-2.35) 59(7.62,2.35) 60(7.62,-2.35) 61(8.255,2.35) 62(8.255,-2.35) 63(8.89,2.35) 64(8.89,-2.35) 65(9.525,2.35) 66(9.525,-2.35) 67(10.16,2.35) 68(10.16,-2.35) 69(10.795,2.35) 70(10.795,-2.35)
  round 0.7 hole 0.7: 1(12.05,0)
  rect 2.5x2 smd: M1(-13.863,0) M2(13.863,0)
Top Overlay:
  lines w0.203: -14.362,-1.5 -14.962,-1.5 -14.962,-3.1 -12.962,-3.1 -12.962,-2.4 ; -14.362,1.5 -14.962,1.5 -14.962,1.875 -13.738,3.1 -12.962,3.1 -12.962,2.4 ; -11.362,-2 -13.112,-2 -13.112,0 -12.362,0 -12.362,2 -11.362,2 ; -11.362,-1 cw(c-11.363,-0.75) -11.613,-0.75 -11.613,0.75 cw(c-11.363,0.75) -11.362,1 ; 11.362,-2 13.112,-2 13.112,0 12.362,0 12.362,2 11.362,2 ; 11.362,-1 ccw(c11.363,-0.75) 11.613,-0.75 11.613,0.75 ccw(c11.363,0.75) 11.362,1 ; 12.962,-2.4 12.962,-3.1 14.962,-3.1 14.962,-1.5 14.362,-1.5 ; 12.962,2.4 12.962,3.1 14.962,3.1 14.962,1.5 14.362,1.5
Top Solder:
  rectangle: -10.995,1.075 -10.595,3.625
  region: -10.595,-1.075 -10.995,-1.075 -10.995,-3.625 -10.595,-3.625
  rectangle: -10.36,1.075 -9.96,3.625
  region: -9.96,-1.075 -10.36,-1.075 -10.36,-3.625 -9.96,-3.625
  rectangle: -9.725,1.075 -9.325,3.625
  region: -9.325,-1.075 -9.725,-1.075 -9.725,-3.625 -9.325,-3.625
  rectangle: -9.09,1.075 -8.69,3.625
  region: -8.69,-1.075 -9.09,-1.075 -9.09,-3.625 -8.69,-3.625
  rectangle: -8.455,1.075 -8.055,3.625
  region: -8.055,-1.075 -8.455,-1.075 -8.455,-3.625 -8.055,-3.625
  rectangle: -7.82,1.075 -7.42,3.625
  region: -7.42,-1.075 -7.82,-1.075 -7.82,-3.625 -7.42,-3.625
  rectangle: -7.185,1.075 -6.785,3.625
  region: -6.785,-1.075 -7.185,-1.075 -7.185,-3.625 -6.785,-3.625
  rectangle: -6.55,1.075 -6.15,3.625
  region: -6.15,-1.075 -6.55,-1.075 -6.55,-3.625 -6.15,-3.625
  rectangle: -5.915,1.075 -5.515,3.625
  region: -5.515,-1.075 -5.915,-1.075 -5.915,-3.625 -5.515,-3.625
  rectangle: -5.28,1.075 -4.88,3.625
  region: -4.88,-1.075 -5.28,-1.075 -5.28,-3.625 -4.88,-3.625
  rectangle: -4.645,1.075 -4.245,3.625
  region: -4.245,-1.075 -4.645,-1.075 -4.645,-3.625 -4.245,-3.625
  rectangle: -4.01,1.075 -3.61,3.625
  region: -3.61,-1.075 -4.01,-1.075 -4.01,-3.625 -3.61,-3.625
  rectangle: -3.375,1.075 -2.975,3.625
  region: -2.975,-1.075 -3.375,-1.075 -3.375,-3.625 -2.975,-3.625
  rectangle: -2.74,1.075 -2.34,3.625
  region: -2.34,-1.075 -2.74,-1.075 -2.74,-3.625 -2.34,-3.625
  rectangle: -2.105,1.075 -1.705,3.625
  region: -1.705,-1.075 -2.105,-1.075 -2.105,-3.625 -1.705,-3.625
  rectangle: -1.47,1.075 -1.07,3.625
  region: -1.07,-1.075 -1.47,-1.075 -1.47,-3.625 -1.07,-3.625
  rectangle: -0.835,1.075 -0.435,3.625
  region: -0.435,-1.075 -0.835,-1.075 -0.835,-3.625 -0.435,-3.625
  rectangle: -0.2,1.075 0.2,3.625
  region: 0.2,-1.075 -0.2,-1.075 -0.2,-3.625 0.2,-3.625
  rectangle: 0.435,1.075 0.835,3.625
  region: 0.835,-1.075 0.435,-1.075 0.435,-3.625 0.835,-3.625
  rectangle: 1.07,1.075 1.47,3.625
  region: 1.47,-1.075 1.07,-1.075 1.07,-3.625 1.47,-3.625
  rectangle: 1.705,1.075 2.105,3.625
  region: 2.105,-1.075 1.705,-1.075 1.705,-3.625 2.105,-3.625
  rectangle: 2.34,1.075 2.74,3.625
  region: 2.74,-1.075 2.34,-1.075 2.34,-3.625 2.74,-3.625
  rectangle: 2.975,1.075 3.375,3.625
  region: 3.375,-1.075 2.975,-1.075 2.975,-3.625 3.375,-3.625
  rectangle: 3.61,1.075 4.01,3.625
  region: 4.01,-1.075 3.61,-1.075 3.61,-3.625 4.01,-3.625
  rectangle: 4.245,1.075 4.645,3.625
  region: 4.645,-1.075 4.245,-1.075 4.245,-3.625 4.645,-3.625
  rectangle: 4.88,1.075 5.28,3.625
  region: 5.28,-1.075 4.88,-1.075 4.88,-3.625 5.28,-3.625
  rectangle: 5.515,1.075 5.915,3.625
  region: 5.915,-1.075 5.515,-1.075 5.515,-3.625 5.915,-3.625
  rectangle: 6.15,1.075 6.55,3.625
  region: 6.55,-1.075 6.15,-1.075 6.15,-3.625 6.55,-3.625
  rectangle: 6.785,1.075 7.185,3.625
  region: 7.185,-1.075 6.785,-1.075 6.785,-3.625 7.185,-3.625
  rectangle: 7.42,1.075 7.82,3.625
  region: 7.82,-1.075 7.42,-1.075 7.42,-3.625 7.82,-3.625
  rectangle: 8.055,1.075 8.455,3.625
  region: 8.455,-1.075 8.055,-1.075 8.055,-3.625 8.455,-3.625
  rectangle: 8.69,1.075 9.09,3.625
  region: 9.09,-1.075 8.69,-1.075 8.69,-3.625 9.09,-3.625
  rectangle: 9.325,1.075 9.725,3.625
  region: 9.725,-1.075 9.325,-1.075 9.325,-3.625 9.725,-3.625
  rectangle: 9.96,1.075 10.36,3.625
  region: 10.36,-1.075 9.96,-1.075 9.96,-3.625 10.36,-3.625
  rectangle: 10.595,1.075 10.995,3.625
  region: 10.995,-1.075 10.595,-1.075 10.595,-3.625 10.995,-3.625
Mechanical 16:
  rectangle: -10.945,-3.1 -10.645,-2.375
  region: -10.645,3.1 -10.945,3.1 -10.945,2.375 -10.645,2.375
  rectangle: -10.31,-3.1 -10.01,-2.375
  region: -10.01,3.1 -10.31,3.1 -10.31,2.375 -10.01,2.375
  rectangle: -9.675,-3.1 -9.375,-2.375
  region: -9.375,3.1 -9.675,3.1 -9.675,2.375 -9.375,2.375
  rectangle: -9.04,-3.1 -8.74,-2.375
  region: -8.74,3.1 -9.04,3.1 -9.04,2.375 -8.74,2.375
  rectangle: -8.405,-3.1 -8.105,-2.375
  region: -8.105,3.1 -8.405,3.1 -8.405,2.375 -8.105,2.375
  rectangle: -7.77,-3.1 -7.47,-2.375
  region: -7.47,3.1 -7.77,3.1 -7.77,2.375 -7.47,2.375
  rectangle: -7.135,-3.1 -6.835,-2.375
  region: -6.835,3.1 -7.135,3.1 -7.135,2.375 -6.835,2.375
  rectangle: -6.5,-3.1 -6.2,-2.375
  region: -6.2,3.1 -6.5,3.1 -6.5,2.375 -6.2,2.375
  rectangle: -5.865,-3.1 -5.565,-2.375
  region: -5.565,3.1 -5.865,3.1 -5.865,2.375 -5.565,2.375
  rectangle: -5.23,-3.1 -4.93,-2.375
  region: -4.93,3.1 -5.23,3.1 -5.23,2.375 -4.93,2.375
  rectangle: -4.595,-3.1 -4.295,-2.375
  region: -4.295,3.1 -4.595,3.1 -4.595,2.375 -4.295,2.375
  rectangle: -3.96,-3.1 -3.66,-2.375
  region: -3.66,3.1 -3.96,3.1 -3.96,2.375 -3.66,2.375
  rectangle: -3.325,-3.1 -3.025,-2.375
  region: -3.025,3.1 -3.325,3.1 -3.325,2.375 -3.025,2.375
  rectangle: -2.69,-3.1 -2.39,-2.375
  region: -2.39,3.1 -2.69,3.1 -2.69,2.375 -2.39,2.375
  rectangle: -2.055,-3.1 -1.755,-2.375
  region: -1.755,3.1 -2.055,3.1 -2.055,2.375 -1.755,2.375
  rectangle: -1.42,-3.1 -1.12,-2.375
  region: -1.12,3.1 -1.42,3.1 -1.42,2.375 -1.12,2.375
  rectangle: -0.785,-3.1 -0.485,-2.375
  region: -0.485,3.1 -0.785,3.1 -0.785,2.375 -0.485,2.375
  rectangle: -0.15,-3.1 0.15,-2.375
  region: 0.15,3.1 -0.15,3.1 -0.15,2.375 0.15,2.375
  rectangle: 0.485,-3.1 0.785,-2.375
  region: 0.785,3.1 0.485,3.1 0.485,2.375 0.785,2.375
  rectangle: 1.12,-3.1 1.42,-2.375
  region: 1.42,3.1 1.12,3.1 1.12,2.375 1.42,2.375
  rectangle: 1.755,-3.1 2.055,-2.375
  region: 2.055,3.1 1.755,3.1 1.755,2.375 2.055,2.375
  rectangle: 2.39,-3.1 2.69,-2.375
  region: 2.69,3.1 2.39,3.1 2.39,2.375 2.69,2.375
  rectangle: 3.025,-3.1 3.325,-2.375
  region: 3.325,3.1 3.025,3.1 3.025,2.375 3.325,2.375
  rectangle: 3.66,-3.1 3.96,-2.375
  region: 3.96,3.1 3.66,3.1 3.66,2.375 3.96,2.375
  rectangle: 4.295,-3.1 4.595,-2.375
  region: 4.595,3.1 4.295,3.1 4.295,2.375 4.595,2.375
  rectangle: 4.93,-3.1 5.23,-2.375
  region: 5.23,3.1 4.93,3.1 4.93,2.375 5.23,2.375
  rectangle: 5.565,-3.1 5.865,-2.375
  region: 5.865,3.1 5.565,3.1 5.565,2.375 5.865,2.375
  rectangle: 6.2,-3.1 6.5,-2.375
  region: 6.5,3.1 6.2,3.1 6.2,2.375 6.5,2.375
  rectangle: 6.835,-3.1 7.135,-2.375
  region: 7.135,3.1 6.835,3.1 6.835,2.375 7.135,2.375
  rectangle: 7.47,-3.1 7.77,-2.375
  region: 7.77,3.1 7.47,3.1 7.47,2.375 7.77,2.375
  rectangle: 8.105,-3.1 8.405,-2.375
  region: 8.405,3.1 8.105,3.1 8.105,2.375 8.405,2.375
  rectangle: 8.74,-3.1 9.04,-2.375
  region: 9.04,3.1 8.74,3.1 8.74,2.375 9.04,2.375
  rectangle: 9.375,-3.1 9.675,-2.375
  region: 9.675,3.1 9.375,3.1 9.375,2.375 9.675,2.375
  rectangle: 10.01,-3.1 10.31,-2.375
  region: 10.31,3.1 10.01,3.1 10.01,2.375 10.31,2.375
  rectangle: 10.645,-3.1 10.945,-2.375
  region: 10.945,3.1 10.645,3.1 10.645,2.375 10.945,2.375
  lines w0.203: -14.362,-1.5 -14.362,1.5 ; -12.962,-2.4 12.962,-2.4 ; -12.962,2.4 12.962,2.4 ; -11.362,-2 11.362,-2 ; -11.362,-1 11.362,-1 ; -11.362,1 11.362,1 ; -11.362,2 11.362,2 ; 14.362,-1.5 14.362,1.5

## 55091-0809 [mm]
pads (84):
  round 0.9 hole 0.9: 1(-13.635,0)
  rect 0.35x2.5 smd: 1(-12.383,2.35) 2(-12.383,-2.35) 3(-11.747,2.35) 4(-11.747,-2.35) 5(-11.112,2.35) 6(-11.112,-2.35) 7(-10.477,2.35) 8(-10.477,-2.35) 9(-9.842,2.35) 10(-9.842,-2.35) 11(-9.207,2.35) 12(-9.207,-2.35) 13(-8.572,2.35) 14(-8.572,-2.35) 15(-7.938,2.35) 16(-7.938,-2.35) 17(-7.302,2.35) 18(-7.302,-2.35) 19(-6.667,2.35) 20(-6.667,-2.35) 21(-6.032,2.35) 22(-6.032,-2.35) 23(-5.397,2.35) 24(-5.397,-2.35) 25(-4.763,2.35) 26(-4.763,-2.35) 27(-4.127,2.35) 28(-4.127,-2.35) 29(-3.492,2.35) 30(-3.492,-2.35) 31(-2.857,2.35) 32(-2.857,-2.35) 33(-2.222,2.35) 34(-2.222,-2.35) 35(-1.587,2.35) 36(-1.587,-2.35) 37(-0.953,2.35) 38(-0.953,-2.35) 39(-0.318,2.35) 40(-0.318,-2.35) 41(0.318,2.35) 42(0.318,-2.35) 43(0.953,2.35) 44(0.953,-2.35) 45(1.587,2.35) 46(1.587,-2.35) 47(2.222,2.35) 48(2.222,-2.35) 49(2.857,2.35) 50(2.857,-2.35) 51(3.492,2.35) 52(3.492,-2.35) 53(4.127,2.35) 54(4.127,-2.35) 55(4.763,2.35) 56(4.763,-2.35) 57(5.397,2.35) 58(5.397,-2.35) 59(6.032,2.35) 60(6.032,-2.35) 61(6.667,2.35) 62(6.667,-2.35) 63(7.302,2.35) 64(7.302,-2.35) 65(7.938,2.35) 66(7.938,-2.35) 67(8.572,2.35) 68(8.572,-2.35) 69(9.207,2.35) 70(9.207,-2.35) 71(9.842,2.35) 72(9.842,-2.35) 73(10.477,2.35) 74(10.477,-2.35) 75(11.112,2.35) 76(11.112,-2.35) 77(11.747,2.35) 78(11.747,-2.35) 79(12.383,2.35) 80(12.383,-2.35)
  round 0.7 hole 0.7: 1(13.635,0)
  rect 2.5x2 smd: M1(-15.45,-0.025) M2(15.45,0)
Top Overlay:
  lines w0.203: -15.95,-1.5 -16.55,-1.5 -16.55,-3.1 -14.55,-3.1 -14.55,-2.4 ; -15.95,1.5 -16.55,1.5 -16.55,1.875 -15.325,3.1 -14.55,3.1 -14.55,2.4 ; -12.95,-2 -14.7,-2 -14.7,0 -13.95,0 -13.95,2 -12.95,2 ; -12.95,-1 cw(c-12.95,-0.75) -13.2,-0.75 -13.2,0.75 cw(c-12.95,0.75) -12.95,1 ; 12.95,-2 14.7,-2 14.7,0 13.95,0 13.95,2 12.95,2 ; 12.95,-1 ccw(c12.95,-0.75) 13.2,-0.75 13.2,0.75 ccw(c12.95,0.75) 12.95,1 ; 14.55,-2.4 14.55,-3.1 16.55,-3.1 16.55,-1.5 15.95,-1.5 ; 14.55,2.4 14.55,3.1 16.55,3.1 16.55,1.5 15.95,1.5
Top Solder:
  rectangle: -12.582,1.075 -12.183,3.625
  region: -12.183,-1.075 -12.582,-1.075 -12.582,-3.625 -12.183,-3.625
  rectangle: -11.947,1.075 -11.548,3.625
  region: -11.548,-1.075 -11.947,-1.075 -11.947,-3.625 -11.548,-3.625
  rectangle: -11.312,1.075 -10.913,3.625
  region: -10.913,-1.075 -11.312,-1.075 -11.312,-3.625 -10.913,-3.625
  rectangle: -10.677,1.075 -10.278,3.625
  region: -10.278,-1.075 -10.677,-1.075 -10.677,-3.625 -10.278,-3.625
  rectangle: -10.042,1.075 -9.643,3.625
  region: -9.643,-1.075 -10.042,-1.075 -10.042,-3.625 -9.643,-3.625
  rectangle: -9.407,1.075 -9.008,3.625
  region: -9.008,-1.075 -9.407,-1.075 -9.407,-3.625 -9.008,-3.625
  rectangle: -8.772,1.075 -8.373,3.625
  region: -8.373,-1.075 -8.772,-1.075 -8.772,-3.625 -8.373,-3.625
  rectangle: -8.137,1.075 -7.738,3.625
  region: -7.738,-1.075 -8.137,-1.075 -8.137,-3.625 -7.738,-3.625
  rectangle: -7.502,1.075 -7.103,3.625
  region: -7.103,-1.075 -7.502,-1.075 -7.502,-3.625 -7.103,-3.625
  rectangle: -6.867,1.075 -6.468,3.625
  region: -6.468,-1.075 -6.867,-1.075 -6.867,-3.625 -6.468,-3.625
  rectangle: -6.232,1.075 -5.833,3.625
  region: -5.833,-1.075 -6.232,-1.075 -6.232,-3.625 -5.833,-3.625
  rectangle: -5.597,1.075 -5.198,3.625
  region: -5.198,-1.075 -5.597,-1.075 -5.597,-3.625 -5.198,-3.625
  rectangle: -4.962,1.075 -4.563,3.625
  region: -4.563,-1.075 -4.962,-1.075 -4.962,-3.625 -4.563,-3.625
  rectangle: -4.327,1.075 -3.928,3.625
  region: -3.928,-1.075 -4.327,-1.075 -4.327,-3.625 -3.928,-3.625
  rectangle: -3.692,1.075 -3.293,3.625
  region: -3.293,-1.075 -3.692,-1.075 -3.692,-3.625 -3.293,-3.625
  rectangle: -3.057,1.075 -2.658,3.625
  region: -2.658,-1.075 -3.057,-1.075 -3.057,-3.625 -2.658,-3.625
  rectangle: -2.422,1.075 -2.023,3.625
  region: -2.023,-1.075 -2.422,-1.075 -2.422,-3.625 -2.023,-3.625
  rectangle: -1.787,1.075 -1.388,3.625
  region: -1.388,-1.075 -1.787,-1.075 -1.787,-3.625 -1.388,-3.625
  rectangle: -1.152,1.075 -0.753,3.625
  region: -0.753,-1.075 -1.152,-1.075 -1.152,-3.625 -0.753,-3.625
  rectangle: -0.517,1.075 -0.118,3.625
  region: -0.118,-1.075 -0.517,-1.075 -0.517,-3.625 -0.118,-3.625
  rectangle: 0.118,1.075 0.517,3.625
  region: 0.517,-1.075 0.118,-1.075 0.118,-3.625 0.517,-3.625
  rectangle: 0.753,1.075 1.152,3.625
  region: 1.152,-1.075 0.753,-1.075 0.753,-3.625 1.152,-3.625
  rectangle: 1.388,1.075 1.787,3.625
  region: 1.787,-1.075 1.388,-1.075 1.388,-3.625 1.787,-3.625
  rectangle: 2.023,1.075 2.422,3.625
  region: 2.422,-1.075 2.023,-1.075 2.023,-3.625 2.422,-3.625
  rectangle: 2.658,1.075 3.057,3.625
  region: 3.057,-1.075 2.658,-1.075 2.658,-3.625 3.057,-3.625
  rectangle: 3.293,1.075 3.692,3.625
  region: 3.692,-1.075 3.293,-1.075 3.293,-3.625 3.692,-3.625
  rectangle: 3.928,1.075 4.327,3.625
  region: 4.327,-1.075 3.928,-1.075 3.928,-3.625 4.327,-3.625
  rectangle: 4.563,1.075 4.962,3.625
  region: 4.962,-1.075 4.563,-1.075 4.563,-3.625 4.962,-3.625
  rectangle: 5.198,1.075 5.597,3.625
  region: 5.597,-1.075 5.198,-1.075 5.198,-3.625 5.597,-3.625
  rectangle: 5.833,1.075 6.232,3.625
  region: 6.232,-1.075 5.833,-1.075 5.833,-3.625 6.232,-3.625
  rectangle: 6.468,1.075 6.867,3.625
  region: 6.867,-1.075 6.468,-1.075 6.468,-3.625 6.867,-3.625
  rectangle: 7.103,1.075 7.502,3.625
  region: 7.502,-1.075 7.103,-1.075 7.103,-3.625 7.502,-3.625
  rectangle: 7.738,1.075 8.137,3.625
  region: 8.137,-1.075 7.738,-1.075 7.738,-3.625 8.137,-3.625
  rectangle: 8.373,1.075 8.772,3.625
  region: 8.772,-1.075 8.373,-1.075 8.373,-3.625 8.772,-3.625
  rectangle: 9.008,1.075 9.407,3.625
  region: 9.407,-1.075 9.008,-1.075 9.008,-3.625 9.407,-3.625
  rectangle: 9.643,1.075 10.042,3.625
  region: 10.042,-1.075 9.643,-1.075 9.643,-3.625 10.042,-3.625
  rectangle: 10.278,1.075 10.677,3.625
  region: 10.677,-1.075 10.278,-1.075 10.278,-3.625 10.677,-3.625
  rectangle: 10.913,1.075 11.312,3.625
  region: 11.312,-1.075 10.913,-1.075 10.913,-3.625 11.312,-3.625
  rectangle: 11.548,1.075 11.947,3.625
  region: 11.947,-1.075 11.548,-1.075 11.548,-3.625 11.947,-3.625
  rectangle: 12.183,1.075 12.582,3.625
  region: 12.582,-1.075 12.183,-1.075 12.183,-3.625 12.582,-3.625
Mechanical 16:
  rectangle: -12.533,-3.1 -12.232,-2.375
  region: -12.232,3.1 -12.533,3.1 -12.533,2.375 -12.232,2.375
  rectangle: -11.898,-3.1 -11.597,-2.375
  region: -11.597,3.1 -11.898,3.1 -11.898,2.375 -11.597,2.375
  rectangle: -11.263,-3.1 -10.962,-2.375
  region: -10.962,3.1 -11.263,3.1 -11.263,2.375 -10.962,2.375
  rectangle: -10.628,-3.1 -10.327,-2.375
  region: -10.327,3.1 -10.628,3.1 -10.628,2.375 -10.327,2.375
  rectangle: -9.993,-3.1 -9.692,-2.375
  region: -9.692,3.1 -9.993,3.1 -9.993,2.375 -9.692,2.375
  rectangle: -9.358,-3.1 -9.057,-2.375
  region: -9.057,3.1 -9.358,3.1 -9.358,2.375 -9.057,2.375
  rectangle: -8.723,-3.1 -8.422,-2.375
  region: -8.422,3.1 -8.723,3.1 -8.723,2.375 -8.422,2.375
  rectangle: -8.088,-3.1 -7.787,-2.375
  region: -7.787,3.1 -8.088,3.1 -8.088,2.375 -7.787,2.375
  rectangle: -7.453,-3.1 -7.152,-2.375
  region: -7.152,3.1 -7.453,3.1 -7.453,2.375 -7.152,2.375
  rectangle: -6.818,-3.1 -6.517,-2.375
  region: -6.517,3.1 -6.818,3.1 -6.818,2.375 -6.517,2.375
  rectangle: -6.183,-3.1 -5.882,-2.375
  region: -5.882,3.1 -6.183,3.1 -6.183,2.375 -5.882,2.375
  rectangle: -5.548,-3.1 -5.247,-2.375
  region: -5.247,3.1 -5.548,3.1 -5.548,2.375 -5.247,2.375
  rectangle: -4.913,-3.1 -4.612,-2.375
  region: -4.612,3.1 -4.913,3.1 -4.913,2.375 -4.612,2.375
  rectangle: -4.278,-3.1 -3.977,-2.375
  region: -3.977,3.1 -4.278,3.1 -4.278,2.375 -3.977,2.375
  rectangle: -3.643,-3.1 -3.342,-2.375
  region: -3.342,3.1 -3.643,3.1 -3.643,2.375 -3.342,2.375
  rectangle: -3.008,-3.1 -2.707,-2.375
  region: -2.707,3.1 -3.008,3.1 -3.008,2.375 -2.707,2.375
  rectangle: -2.373,-3.1 -2.072,-2.375
  region: -2.072,3.1 -2.373,3.1 -2.373,2.375 -2.072,2.375
  rectangle: -1.738,-3.1 -1.437,-2.375
  region: -1.437,3.1 -1.738,3.1 -1.738,2.375 -1.437,2.375
  rectangle: -1.103,-3.1 -0.802,-2.375
  region: -0.802,3.1 -1.103,3.1 -1.103,2.375 -0.802,2.375
  rectangle: -0.468,-3.1 -0.167,-2.375
  region: -0.167,3.1 -0.468,3.1 -0.468,2.375 -0.167,2.375
  rectangle: 0.167,-3.1 0.468,-2.375
  region: 0.468,3.1 0.167,3.1 0.167,2.375 0.468,2.375
  rectangle: 0.802,-3.1 1.103,-2.375
  region: 1.103,3.1 0.802,3.1 0.802,2.375 1.103,2.375
  rectangle: 1.437,-3.1 1.738,-2.375
  region: 1.738,3.1 1.437,3.1 1.437,2.375 1.738,2.375
  rectangle: 2.072,-3.1 2.373,-2.375
  region: 2.373,3.1 2.072,3.1 2.072,2.375 2.373,2.375
  rectangle: 2.707,-3.1 3.008,-2.375
  region: 3.008,3.1 2.707,3.1 2.707,2.375 3.008,2.375
  rectangle: 3.342,-3.1 3.643,-2.375
  region: 3.643,3.1 3.342,3.1 3.342,2.375 3.643,2.375
  rectangle: 3.977,-3.1 4.278,-2.375
  region: 4.278,3.1 3.977,3.1 3.977,2.375 4.278,2.375
  rectangle: 4.612,-3.1 4.913,-2.375
  region: 4.913,3.1 4.612,3.1 4.612,2.375 4.913,2.375
  rectangle: 5.247,-3.1 5.548,-2.375
  region: 5.548,3.1 5.247,3.1 5.247,2.375 5.548,2.375
  rectangle: 5.882,-3.1 6.183,-2.375
  region: 6.183,3.1 5.882,3.1 5.882,2.375 6.183,2.375
  rectangle: 6.517,-3.1 6.818,-2.375
  region: 6.818,3.1 6.517,3.1 6.517,2.375 6.818,2.375
  rectangle: 7.152,-3.1 7.453,-2.375
  region: 7.453,3.1 7.152,3.1 7.152,2.375 7.453,2.375
  rectangle: 7.787,-3.1 8.088,-2.375
  region: 8.088,3.1 7.787,3.1 7.787,2.375 8.088,2.375
  rectangle: 8.422,-3.1 8.723,-2.375
  region: 8.723,3.1 8.422,3.1 8.422,2.375 8.723,2.375
  rectangle: 9.057,-3.1 9.358,-2.375
  region: 9.358,3.1 9.057,3.1 9.057,2.375 9.358,2.375
  rectangle: 9.692,-3.1 9.993,-2.375
  region: 9.993,3.1 9.692,3.1 9.692,2.375 9.993,2.375
  rectangle: 10.327,-3.1 10.628,-2.375
  region: 10.628,3.1 10.327,3.1 10.327,2.375 10.628,2.375
  rectangle: 10.962,-3.1 11.263,-2.375
  region: 11.263,3.1 10.962,3.1 10.962,2.375 11.263,2.375
  rectangle: 11.597,-3.1 11.898,-2.375
  region: 11.898,3.1 11.597,3.1 11.597,2.375 11.898,2.375
  rectangle: 12.232,-3.1 12.533,-2.375
  region: 12.533,3.1 12.232,3.1 12.232,2.375 12.533,2.375
  lines w0.203: -15.95,-1.5 -15.95,1.5 ; -14.55,-2.4 14.55,-2.4 ; -14.55,2.4 14.55,2.4 ; -12.95,-2 12.95,-2 ; -12.95,-1 12.95,-1 ; -12.95,1 12.95,1 ; -12.95,2 12.95,2 ; 15.95,-1.5 15.95,1.5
